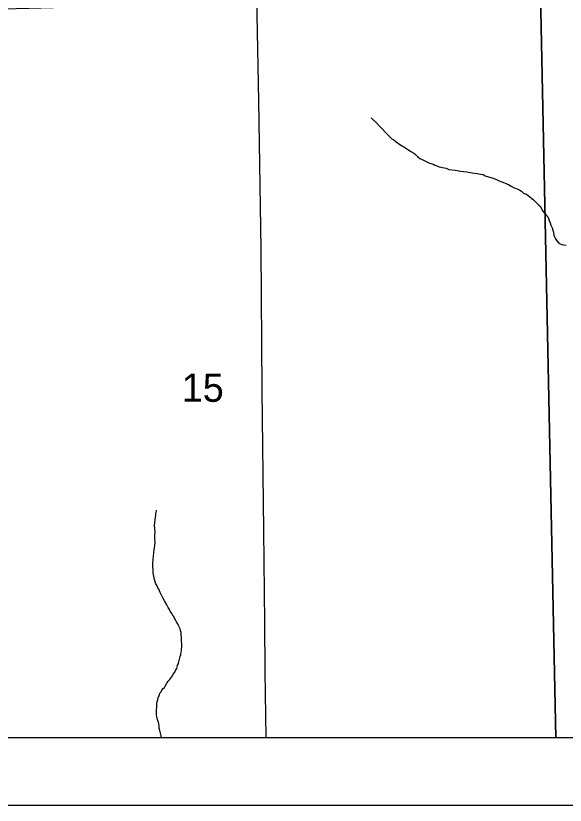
# Model space of a CAD drawing. Extents: x 10.6 to 44.6, y -2.6 to 23.4.
# Drawn here: x 17.431 to 18.244, y 15.426 to 16.595 of the extents above; entities that cross this region are included whole.
import ezdxf

# ---------------------------------------------------------------- set-up
doc = ezdxf.new("R2010")
doc.units = 0
for name, color, linetype in [('GM_X_County', 7, 'Continuous'), ('GM_X_Minor_River', 7, 'Continuous'), ('GM_X_Section', 7, 'Continuous'), ('GM_X_Section_Text', 7, 'Continuous'), ('GM_X_State_Route', 7, 'Continuous'), ('GM_X_Township', 7, 'Continuous'), ('SH_Data', 7, 'Continuous')]:
    doc.layers.add(name, color=color, linetype=linetype)

msp = doc.modelspace()

# ---------------------------------------------------------------- linework, layer by layer
at = {"layer": 'GM_X_County'}
msp.add_lwpolyline([(20.0033, 15.5302), (20.0033, 22.3267), (13.2033, 22.3267), (13.2033, 15.5267), (19.8413, 15.5267)], dxfattribs=at)
at = {"layer": 'GM_X_Minor_River'}
for points in [[(17.9569, 16.4437), (17.9593, 16.4412), (17.9639, 16.4367), (17.9686, 16.4319), (17.9733, 16.4271), (17.9772, 16.4226), (17.9807, 16.4192), (17.983, 16.4174), (17.985, 16.4151), (17.9873, 16.4129), (17.9904, 16.4111), (17.9939, 16.4081), (17.9993, 16.4044), (18.0051, 16.4008), (18.0105, 16.3975), (18.0155, 16.3942), (18.0198, 16.3916), (18.0225, 16.3897), (18.0252, 16.3868), (18.0287, 16.3838), (18.0322, 16.382), (18.0352, 16.3805), (18.0383, 16.3791), (18.0429, 16.3769), (18.0452, 16.3762), (18.0483, 16.3751), (18.051, 16.3736), (18.0537, 16.3726), (18.0571, 16.3715), (18.0621, 16.3701), (18.0675, 16.3691), (18.0717, 16.3673), (18.0812, 16.3663), (18.0892, 16.365), (18.098, 16.3637), (18.106, 16.3623), (18.1133, 16.3614), (18.1186, 16.3603), (18.1225, 16.3597), (18.1255, 16.3582), (18.1374, 16.3543), (18.1432, 16.3521), (18.147, 16.3503), (18.1516, 16.3485), (18.1559, 16.3467), (18.1597, 16.3449), (18.1639, 16.3427), (18.1674, 16.3409), (18.1713, 16.3391), (18.1739, 16.338), (18.1766, 16.3365), (18.179, 16.3351), (18.1821, 16.3325), (18.1863, 16.3307), (18.189, 16.3288), (18.1917, 16.327), (18.194, 16.3248), (18.1968, 16.3222), (18.2003, 16.3188), (18.2034, 16.3162), (18.2049, 16.3144), (18.2069, 16.3129), (18.2105, 16.3057), (18.2136, 16.302), (18.2163, 16.2994), (18.2179, 16.2975), (18.2191, 16.2949), (18.2203, 16.2919), (18.2215, 16.2885), (18.2227, 16.2847), (18.2243, 16.2809), (18.2256, 16.2775), (18.2264, 16.2745), (18.2272, 16.27), (18.2285, 16.2669), (18.2297, 16.2647), (18.2312, 16.2617), (18.2344, 16.2583), (18.2363, 16.2572), (18.2386, 16.2565), (18.2413, 16.2558), (18.2451, 16.2551)], [(17.6366, 15.8262), (17.6368, 15.8311), (17.6364, 15.8361), (17.6362, 15.8406), (17.6365, 15.8448), (17.6368, 15.8487), (17.6375, 15.8521), (17.6378, 15.8551), (17.6381, 15.8582), (17.6385, 15.8601), (17.6388, 15.862), (17.6388, 15.8632)], [(17.6464, 15.5267), (17.646, 15.5289), (17.6456, 15.5311), (17.6439, 15.5372), (17.6431, 15.5402), (17.643, 15.5436), (17.6422, 15.5474), (17.6414, 15.5504), (17.6405, 15.5531), (17.6401, 15.5554), (17.6393, 15.5576), (17.6389, 15.5599), (17.6388, 15.5622), (17.6391, 15.566), (17.639, 15.5683), (17.6394, 15.5713), (17.6393, 15.5744), (17.6396, 15.577), (17.6399, 15.5797), (17.641, 15.5828), (17.6417, 15.5854), (17.6428, 15.5889), (17.6438, 15.5923), (17.6457, 15.5943), (17.6471, 15.5966), (17.649, 15.5993), (17.6509, 15.6009), (17.652, 15.6028), (17.6545, 15.607), (17.6564, 15.6098), (17.6582, 15.6121), (17.6597, 15.614), (17.6612, 15.6159), (17.6626, 15.6179), (17.6637, 15.6202), (17.6659, 15.6233), (17.667, 15.6256), (17.6689, 15.6287), (17.6696, 15.6306), (17.6703, 15.6337), (17.6714, 15.636), (17.6721, 15.6386), (17.6742, 15.6467), (17.6749, 15.649), (17.6752, 15.6509), (17.6759, 15.6551), (17.6762, 15.6578), (17.6765, 15.6604), (17.6765, 15.6627), (17.6764, 15.6658), (17.6759, 15.6688), (17.6759, 15.6726), (17.6758, 15.6753), (17.6757, 15.6783), (17.6753, 15.6821), (17.6744, 15.6844), (17.674, 15.6874), (17.6732, 15.6897), (17.6716, 15.6923), (17.6708, 15.6949), (17.6688, 15.6979), (17.6672, 15.7006), (17.6656, 15.7032), (17.6644, 15.7058), (17.6629, 15.7077), (17.6621, 15.7096), (17.6597, 15.7129), (17.6581, 15.716), (17.6561, 15.719), (17.6542, 15.7231), (17.651, 15.7287), (17.6486, 15.7332), (17.6466, 15.7374), (17.6446, 15.7411), (17.6434, 15.7438), (17.6422, 15.746), (17.641, 15.7483), (17.6398, 15.7509), (17.6382, 15.7539), (17.637, 15.7573), (17.6358, 15.7607), (17.6349, 15.7653), (17.6341, 15.7698), (17.634, 15.7744), (17.6338, 15.7797), (17.6337, 15.785), (17.634, 15.79), (17.6355, 15.8049), (17.6366, 15.8102), (17.6368, 15.8159), (17.6367, 15.8205), (17.6366, 15.8262)]]:
    msp.add_lwpolyline(points, dxfattribs=at)
at = {"layer": 'GM_X_Section'}
for p, q in [((17.2881, 15.5267), (18.2299, 15.5267)), ((18.2299, 15.5267), (19.1603, 15.5267))]:
    msp.add_line(p, q, dxfattribs=at)
for points in [[(18.2299, 15.5267), (18.2074, 16.6265), (17.2647, 16.6007), (17.2881, 15.5267)], [(19.1603, 15.5267), (19.1419, 16.6116), (19.1419, 16.6144), (19.1418, 16.6213), (18.2074, 16.6265), (18.2299, 15.5267)]]:
    msp.add_lwpolyline(points, dxfattribs=at)
at = {"layer": 'GM_X_State_Route'}
msp.add_lwpolyline([(17.8012, 15.5267), (17.7999, 15.6245), (17.7994, 15.6969), (17.798, 15.8329), (17.7956, 16.0407), (17.7937, 16.2499), (17.7904, 16.4688), (17.788, 16.5964), (17.7861, 16.6856), (17.7836, 16.85), (17.7826, 16.9026), (17.7801, 17.0459), (17.7792, 17.124), (17.7789, 17.1502), (17.7773, 17.3034), (17.7765, 17.3624), (17.7744, 17.5784), (17.7731, 17.7202), (17.7723, 17.7811), (17.7695, 17.9272), (17.7683, 17.9968), (17.7654, 18.1426), (17.7636, 18.2173)], dxfattribs=at)
at = {"layer": 'GM_X_Township'}
msp.add_line((15.2903, 15.5267), (19.8413, 15.5267), dxfattribs=at)
at = {"layer": 'SH_Data'}
msp.add_line((13.1028, 15.4265), (20.1028, 15.4265), dxfattribs=at)

# ---------------------------------------------------------------- texts
at = {"layer": 'GM_X_Section_Text'}
msp.add_text('15', height=0.04186, rotation=0, dxfattribs=at).set_placement((17.6763, 16.0235))

doc.saveas('drawing.dxf')
